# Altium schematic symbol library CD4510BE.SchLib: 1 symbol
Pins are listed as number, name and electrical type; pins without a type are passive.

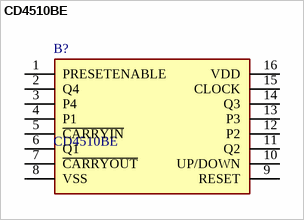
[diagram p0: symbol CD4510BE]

## CD4510BE
designator B?
CD4510BE, 4-stage BCD Counter, Decade Up/Down Counter, Bi-Directional, 3  18 V, 16-Pin PDIP; Manufacturer_Name: Texas Instruments; Geometry.Height: 5.08mm
footprint DIP794W53P254L1930H508Q16N
pins: 1 PRESETENABLE, 2 Q4, 3 P4, 4 P1, 5 ~{CARRYIN}, 6 Q1, 7 ~{CARRYOUT}, 8 VSS (power), 9 RESET, 10 UP/DOWN, 11 Q2, 12 P2, 13 P3, 14 Q3, 15 CLOCK, 16 VDD (power)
